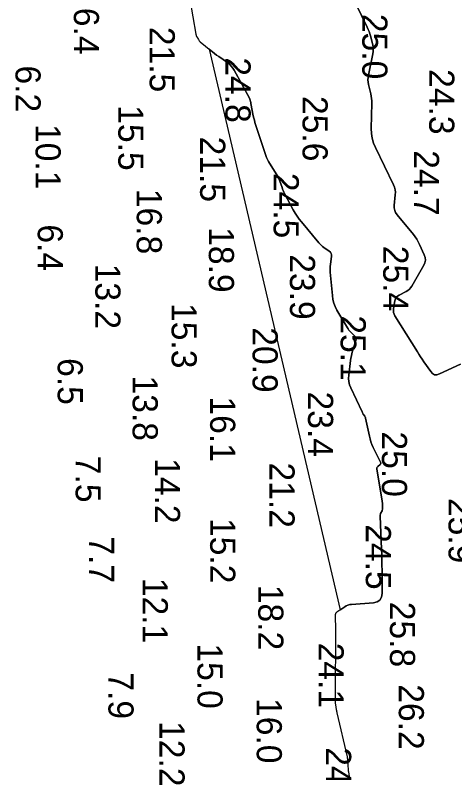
# Model space of a CAD drawing. Extents: x 1178573 to 1187098, y 693282 to 751751.
# Drawn here: x 1183710.4 to 1183929.1, y 749843.2 to 750219.8 of the extents above; entities that cross this region are included whole.
import ezdxf

# ---------------------------------------------------------------- set-up
doc = ezdxf.new("R2010")
doc.units = 0
for name, color, linetype in [('G-ANNO-PATT', 7, 'Continuous'), ('V-HYDS-MAJR', 7, 'Continuous'), ('V-HYDS-SOUN', 7, 'Continuous')]:
    doc.layers.add(name, color=color, linetype=linetype)

msp = doc.modelspace()

# ---------------------------------------------------------------- linework, layer by layer
at = {"layer": 'G-ANNO-PATT'}
msp.add_line((1183807, 750202.9), (1183872.06, 749924.24), dxfattribs=at)
for points in [[(1183879.91, 750225.54), (1183885.58, 750213.82), (1183886.05, 750212.78), (1183886.47, 750211.71), (1183886.83, 750210.63), (1183887.14, 750209.53), (1183888.26, 750205.09), (1183888.47, 750203.98), (1183888.56, 750202.86), (1183888.52, 750201.75), (1183888.35, 750200.63), (1183886.13, 750189.94), (1183885.96, 750188.79), (1183885.91, 750187.64), (1183886, 750186.48), (1183886.21, 750185.34), (1183887.33, 750180.74), (1183887.57, 750179.59), (1183887.73, 750178.43), (1183887.82, 750177.26), (1183887.83, 750176.08), (1183887.52, 750163.49), (1183887.6, 750161.02), (1183887.97, 750158.62), (1183888.63, 750156.29), (1183889.58, 750154.01), (1183898.59, 750135.45), (1183899.08, 750134.26), (1183899.39, 750133.03), (1183899.52, 750131.78), (1183899.48, 750130.49), (1183898.97, 750125.28), (1183898.97, 750124.01), (1183899.2, 750122.82), (1183899.67, 750121.7), (1183900.38, 750120.65), (1183908.51, 750110.77), (1183909.39, 750109.63), (1183910.18, 750108.45), (1183910.9, 750107.21), (1183911.53, 750105.92), (1183913.91, 750100.67), (1183914.34, 750099.37), (1183914.45, 750098.08), (1183914.22, 750096.81), (1183913.67, 750095.55), (1183907.68, 750085.07), (1183907.14, 750084.27), (1183906.5, 750083.57), (1183905.76, 750082.97), (1183904.93, 750082.48), (1183901.39, 750080.73), (1183900.59, 750080.23), (1183899.97, 750079.59), (1183899.54, 750078.81), (1183899.28, 750077.91), (1183898.61, 750073.99), (1183898.53, 750073.03), (1183898.63, 750072.1), (1183898.89, 750071.21), (1183899.33, 750070.35), (1183910.46, 750052.55), (1183911.26, 750051.3), (1183912.07, 750050.05), (1183912.89, 750048.81), (1183913.73, 750047.58), (1183917.1, 750042.67), (1183918, 750041.67), (1183919.03, 750041.14), (1183920.19, 750041.08), (1183921.47, 750041.48), (1183931.86, 750046.36)], [(1183872.06, 749924.24), (1183874.32, 749925.78), (1183875.12, 749926.25), (1183875.95, 749926.61), (1183876.83, 749926.85), (1183877.75, 749926.98), (1183888.65, 749927.8), (1183890.52, 749928.2), (1183891.85, 749929.1), (1183892.64, 749930.5), (1183892.91, 749932.39), (1183892.9, 749943.88), (1183892.88, 749946.5), (1183892.83, 749949.13), (1183892.76, 749951.75), (1183892.65, 749954.38), (1183891.91, 749970.74), (1183891.91, 749971.1), (1183891.97, 749971.46), (1183892.06, 749971.8), (1183892.21, 749972.13), (1183892.89, 749973.45), (1183893.03, 749973.78), (1183893.13, 749974.13), (1183893.19, 749974.48), (1183893.2, 749974.85), (1183893.13, 749976.66), (1183893.11, 749977.09), (1183893.08, 749977.51), (1183893.03, 749977.93), (1183892.96, 749978.35), (1183890.29, 749994.23), (1183890.27, 749994.59), (1183890.34, 749994.91), (1183890.5, 749995.21), (1183890.74, 749995.47), (1183891.9, 749996.46), (1183892.13, 749996.72), (1183892.25, 749997), (1183892.25, 749997.31), (1183892.14, 749997.64), (1183888.52, 750005.01), (1183887.9, 750006.36), (1183887.38, 750007.75), (1183886.94, 750009.17), (1183886.59, 750010.62), (1183884.74, 750019.51), (1183884.67, 750019.8), (1183884.56, 750020.08), (1183884.43, 750020.34), (1183884.27, 750020.59), (1183883.59, 750021.58), (1183883.42, 750021.83), (1183883.26, 750022.09), (1183883.12, 750022.35), (1183882.98, 750022.62), (1183877.32, 750034.65), (1183876.73, 750036.14), (1183876.38, 750037.67), (1183876.25, 750039.23), (1183876.34, 750040.83), (1183877.29, 750048.23), (1183877.46, 750049.38), (1183877.68, 750050.51), (1183877.94, 750051.64), (1183878.25, 750052.75), (1183879.87, 750058.11), (1183879.98, 750058.74), (1183879.92, 750059.33), (1183879.69, 750059.87), (1183879.29, 750060.37), (1183877.34, 750062.29), (1183876.87, 750062.78), (1183876.43, 750063.3), (1183876.04, 750063.85), (1183875.67, 750064.42), (1183870.5, 750073.25), (1183869.62, 750074.95), (1183868.95, 750076.71), (1183868.47, 750078.54), (1183868.2, 750080.44), (1183867.17, 750092.16), (1183867.12, 750093.11), (1183867.11, 750094.06), (1183867.15, 750095.01), (1183867.24, 750095.95), (1183867.75, 750099.99), (1183867.76, 750100.76), (1183867.57, 750101.45), (1183867.19, 750102.04), (1183866.61, 750102.56), (1183863.92, 750104.43), (1183863.27, 750104.92), (1183862.65, 750105.45), (1183862.07, 750106.01), (1183861.53, 750106.62), (1183852.78, 750117.04), (1183851.65, 750118.45), (1183850.61, 750119.92), (1183849.65, 750121.44), (1183848.76, 750123.01), (1183844.47, 750131.13), (1183844.1, 750131.88), (1183843.75, 750132.64), (1183843.44, 750133.42), (1183843.16, 750134.21), (1183842.09, 750137.39), (1183841.8, 750138.18), (1183841.47, 750138.94), (1183841.08, 750139.68), (1183840.65, 750140.4), (1183836.9, 750146.24), (1183836.36, 750147.15), (1183835.89, 750148.08), (1183835.47, 750149.04), (1183835.11, 750150.02), (1183833.81, 750154.04), (1183833.49, 750155.04), (1183833.16, 750156.04), (1183832.83, 750157.04), (1183832.49, 750158.04), (1183830.02, 750165.44), (1183829.69, 750166.5), (1183829.39, 750167.57), (1183829.12, 750168.66), (1183828.89, 750169.75), (1183827.72, 750175.86), (1183827.67, 750176.1), (1183827.62, 750176.33), (1183827.57, 750176.57), (1183827.51, 750176.8), (1183827.26, 750177.73), (1183827.19, 750177.96), (1183827.11, 750178.19), (1183827.01, 750178.41), (1183826.91, 750178.62), (1183819.36, 750192.45), (1183818.68, 750193.55), (1183817.89, 750194.54), (1183817, 750195.44), (1183815.99, 750196.24), (1183811.66, 750199.29), (1183810.64, 750200.02), (1183809.64, 750200.77), (1183808.66, 750201.54), (1183807.69, 750202.33), (1183807, 750202.9)]]:
    msp.add_lwpolyline(points, dxfattribs=at)
at = {"layer": 'V-HYDS-MAJR'}
for points in [[(1183797.33, 750227.83), (1183800.35, 750210.33), (1183800.42, 750209.97), (1183800.53, 750209.63), (1183800.66, 750209.31), (1183800.83, 750208.99), (1183801.54, 750207.73), (1183801.73, 750207.43), (1183801.95, 750207.15), (1183802.19, 750206.89), (1183802.46, 750206.65), (1183807.69, 750202.33), (1183808.66, 750201.54), (1183809.64, 750200.77), (1183810.64, 750200.02), (1183811.66, 750199.29), (1183815.99, 750196.24), (1183817, 750195.44), (1183817.89, 750194.54), (1183818.68, 750193.55), (1183819.36, 750192.45), (1183826.91, 750178.62), (1183827.01, 750178.41), (1183827.11, 750178.19), (1183827.19, 750177.96), (1183827.26, 750177.73), (1183827.51, 750176.8), (1183827.57, 750176.57), (1183827.62, 750176.33), (1183827.67, 750176.1), (1183827.72, 750175.86), (1183828.89, 750169.75), (1183829.12, 750168.66), (1183829.39, 750167.57), (1183829.69, 750166.5), (1183830.02, 750165.44), (1183832.49, 750158.04), (1183832.83, 750157.04), (1183833.16, 750156.04), (1183833.49, 750155.04), (1183833.81, 750154.04), (1183835.11, 750150.02), (1183835.47, 750149.04), (1183835.89, 750148.08), (1183836.36, 750147.15), (1183836.9, 750146.24), (1183840.65, 750140.4), (1183841.08, 750139.68), (1183841.47, 750138.94), (1183841.8, 750138.18), (1183842.09, 750137.39), (1183843.16, 750134.21), (1183843.44, 750133.42), (1183843.75, 750132.64), (1183844.1, 750131.88), (1183844.47, 750131.13), (1183848.76, 750123.01), (1183849.65, 750121.44), (1183850.61, 750119.92), (1183851.65, 750118.45), (1183852.78, 750117.04), (1183861.53, 750106.62), (1183862.07, 750106.01), (1183862.65, 750105.45), (1183863.27, 750104.92), (1183863.92, 750104.43), (1183866.61, 750102.56), (1183867.19, 750102.04), (1183867.57, 750101.45), (1183867.76, 750100.76), (1183867.75, 750099.99), (1183867.24, 750095.95), (1183867.15, 750095.01), (1183867.11, 750094.06), (1183867.12, 750093.11), (1183867.17, 750092.16), (1183868.2, 750080.44), (1183868.47, 750078.54), (1183868.95, 750076.71), (1183869.62, 750074.95), (1183870.5, 750073.25), (1183875.67, 750064.42), (1183876.04, 750063.85), (1183876.43, 750063.3), (1183876.87, 750062.78), (1183877.34, 750062.29), (1183879.29, 750060.37), (1183879.69, 750059.87), (1183879.92, 750059.33), (1183879.98, 750058.74), (1183879.87, 750058.11), (1183878.25, 750052.75), (1183877.94, 750051.64), (1183877.68, 750050.51), (1183877.46, 750049.38), (1183877.29, 750048.23), (1183876.34, 750040.83), (1183876.25, 750039.23), (1183876.38, 750037.67), (1183876.73, 750036.14), (1183877.32, 750034.65), (1183882.98, 750022.62), (1183883.12, 750022.35), (1183883.26, 750022.09), (1183883.42, 750021.83), (1183883.59, 750021.58), (1183884.27, 750020.59), (1183884.43, 750020.34), (1183884.56, 750020.08), (1183884.67, 750019.8), (1183884.74, 750019.51), (1183886.59, 750010.62), (1183886.94, 750009.17), (1183887.38, 750007.75), (1183887.9, 750006.36), (1183888.52, 750005.01), (1183892.14, 749997.64), (1183892.25, 749997.31), (1183892.25, 749997), (1183892.13, 749996.72), (1183891.9, 749996.46), (1183890.74, 749995.47), (1183890.5, 749995.21), (1183890.34, 749994.91), (1183890.27, 749994.59), (1183890.29, 749994.23), (1183892.96, 749978.35), (1183893.03, 749977.93), (1183893.08, 749977.51), (1183893.11, 749977.09), (1183893.13, 749976.66), (1183893.2, 749974.85), (1183893.19, 749974.48), (1183893.13, 749974.13), (1183893.03, 749973.78), (1183892.89, 749973.45), (1183892.21, 749972.13), (1183892.06, 749971.8), (1183891.97, 749971.46), (1183891.91, 749971.1), (1183891.91, 749970.74), (1183892.65, 749954.38), (1183892.76, 749951.75), (1183892.83, 749949.13), (1183892.88, 749946.5), (1183892.9, 749943.88), (1183892.91, 749932.39), (1183892.64, 749930.5), (1183891.85, 749929.1), (1183890.52, 749928.2), (1183888.65, 749927.8), (1183877.75, 749926.98), (1183876.83, 749926.85), (1183875.95, 749926.61), (1183875.12, 749926.25), (1183874.32, 749925.78), (1183870.36, 749923.08), (1183870.06, 749922.83), (1183869.84, 749922.53), (1183869.7, 749922.18), (1183869.65, 749921.78), (1183869.59, 749920.03), (1183869.58, 749919.66), (1183869.58, 749919.29), (1183869.6, 749918.92), (1183869.62, 749918.55), (1183869.74, 749917.08), (1183869.81, 749916.73), (1183869.63, 749877.99), (1183869.62, 749877.92), (1183869.61, 749877.85), (1183869.62, 749877.78), (1183869.63, 749877.71), (1183869.73, 749877.34), (1183869.73, 749877.31), (1183869.74, 749877.29), (1183869.74, 749877.26), (1183869.74, 749877.24), (1183869.74, 749877.14), (1183869.74, 749877.11), (1183869.74, 749877.09), (1183869.74, 749877.06), (1183869.74, 749877.04), (1183870.14, 749874.63), (1183870.21, 749874.22), (1183870.29, 749873.81), (1183870.38, 749873.4), (1183870.47, 749872.99), (1183875.52, 749851.15), (1183875.64, 749850.54), (1183875.74, 749849.92), (1183875.81, 749849.3), (1183875.85, 749848.67), (1183875.94, 749846.16), (1183875.98, 749845.53), (1183876.03, 749844.91), (1183876.09, 749844.28), (1183876.18, 749843.66), (1183879.56, 749821.11)], [(1183931.86, 750046.36), (1183921.47, 750041.48), (1183920.19, 750041.08), (1183919.03, 750041.14), (1183918, 750041.67), (1183917.1, 750042.67), (1183913.73, 750047.58), (1183912.89, 750048.81), (1183912.07, 750050.05), (1183911.26, 750051.3), (1183910.46, 750052.55), (1183899.33, 750070.35), (1183898.89, 750071.21), (1183898.63, 750072.1), (1183898.53, 750073.03), (1183898.61, 750073.99), (1183899.28, 750077.91), (1183899.54, 750078.81), (1183899.97, 750079.59), (1183900.59, 750080.23), (1183901.39, 750080.73), (1183904.93, 750082.48), (1183905.76, 750082.97), (1183906.5, 750083.57), (1183907.14, 750084.27), (1183907.68, 750085.07), (1183913.67, 750095.55), (1183914.22, 750096.81), (1183914.45, 750098.08), (1183914.34, 750099.37), (1183913.91, 750100.67), (1183911.53, 750105.92), (1183910.9, 750107.21), (1183910.18, 750108.45), (1183909.39, 750109.63), (1183908.51, 750110.77), (1183900.38, 750120.65), (1183899.67, 750121.7), (1183899.2, 750122.82), (1183898.97, 750124.01), (1183898.97, 750125.28), (1183899.48, 750130.49), (1183899.52, 750131.78), (1183899.39, 750133.03), (1183899.08, 750134.26), (1183898.59, 750135.45), (1183889.58, 750154.01), (1183888.63, 750156.29), (1183887.97, 750158.62), (1183887.6, 750161.02), (1183887.52, 750163.49), (1183887.83, 750176.08), (1183887.82, 750177.26), (1183887.73, 750178.43), (1183887.57, 750179.59), (1183887.33, 750180.74), (1183886.21, 750185.34), (1183886, 750186.48), (1183885.91, 750187.64), (1183885.96, 750188.79), (1183886.13, 750189.94), (1183888.35, 750200.63), (1183888.52, 750201.75), (1183888.56, 750202.86), (1183888.47, 750203.98), (1183888.26, 750205.09), (1183887.14, 750209.53), (1183886.83, 750210.63), (1183886.47, 750211.71), (1183886.05, 750212.78), (1183885.58, 750213.82), (1183879.91, 750225.54)]]:
    msp.add_lwpolyline(points, dxfattribs=at)

# ---------------------------------------------------------------- texts
at = {"layer": 'V-HYDS-SOUN'}
for s, p in [('16.4 ', (1183739.62, 750232.81)), ('25.0 ', (1183883.09, 750220.5)), ('21.5 ', (1183777.33, 750214.04)), ('24.8 ', (1183815.03, 750198.87)), ('6.2', (1183710.6, 750194.84)), ('24.3 ', (1183916.36, 750193.03)), ('25.6 ', (1183853.37, 750179.68)), ('15.5 ', (1183761.75, 750175.07)), ('10.1 ', (1183720.57, 750165.73)), ('21.5 ', (1183802.43, 750159.48)), ('24.7 ', (1183908.78, 750152.71)), ('24.5 ', (1183839.01, 750141.47)), ('16.8 ', (1183770.9, 750133.52)), ('6.4', (1183721.65, 750115.84)), ('18.9 ', (1183806.76, 750114.46)), ('25.4 ', (1183893.49, 750105.21)), ('23.9 ', (1183847.11, 750101)), ('13.2 ', (1183750.31, 750096.34)), ('15.3 ', (1183788.24, 750076.76)), ('25.1 ', (1183872.31, 750070.65)), ('20.9 ', (1183828.51, 750064.72)), ('6.5', (1183731.59, 750049.39)), ('13.8 ', (1183768.86, 750040.73)), ('16.1 ', (1183807.42, 750030.33)), ('23.4 ', (1183856.09, 750032.77)), ('25.0 ', (1183892.84, 750012.92)), ('7.5', (1183740.52, 750000.83)), ('14.2 ', (1183779.97, 749999.66)), ('21.2 ', (1183836.92, 749997.49)), ('25.9 ', (1183925.98, 749979.88)), ('15.2 ', (1183807.43, 749969.9)), ('24.5 ', (1183884.84, 749966.83)), ('7.7', (1183747.18, 749960.79)), ('12.1 ', (1183773.85, 749940.17)), ('18.2 ', (1183831.34, 749936.7)), ('25.8 ', (1183896.85, 749928.27)), ('15.0 ', (1183801.11, 749907.58)), ('24.1 ', (1183861.35, 749907.92)), ('7.9', (1183756.82, 749893.18)), ('26.2 ', (1183901.23, 749887.26)), ('16.0 ', (1183830.57, 749880.41)), ('12.2 ', (1183782.2, 749868.95)), ('24.1 ', (1183865.06, 749855.95))]:
    msp.add_text(s, height=12.5, rotation=270, dxfattribs=at).set_placement(p)

doc.saveas('drawing.dxf')
